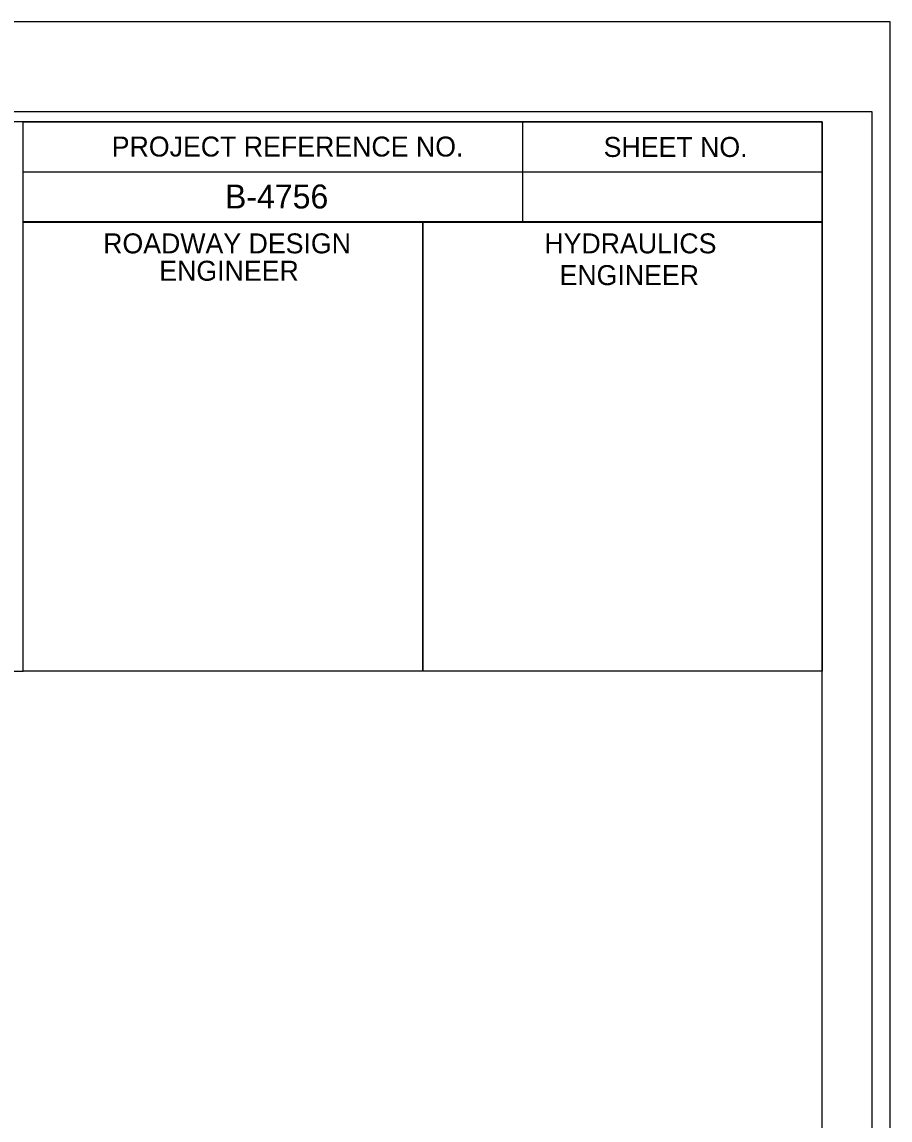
# Model space of a CAD drawing. Extents: x 2431000 to 2534000, y 645879 to 714000.
# Drawn here: x 2465319.4 to 2465536.7, y 677241.9 to 677516.9 of the extents above; entities that cross this region are included whole.
import ezdxf

# ---------------------------------------------------------------- set-up
doc = ezdxf.new("R2010")
doc.units = 0
for name, color, linetype in [('KHA_LOGO', 7, 'Continuous'), ('Sheet Plan CELL', 7, 'Continuous'), ('Sheet Plot Border Inside CELL', 7, 'Continuous'), ('Sheet Plot Border Outside CELL', 7, 'Continuous'), ('Sheet Typical CELL', 7, 'Continuous')]:
    doc.layers.add(name, color=color, linetype=linetype)

msp = doc.modelspace()

# ---------------------------------------------------------------- linework, layer by layer
at = {"layer": 'KHA_LOGO'}
msp.add_lwpolyline([(2465219.65, 677354.33), (2465319.65, 677354.33), (2465319.65, 677491.88), (2465219.65, 677491.88)], close=True, dxfattribs=at)
at = {"layer": 'Sheet Plan CELL'}
for points in [[(2465319.65, 677466.78), (2465419.7, 677466.78), (2465419.7, 677354.28), (2465319.65, 677354.28)], [(2465419.7, 677466.78), (2465519.7, 677466.78), (2465519.7, 677354.28), (2465419.7, 677354.28)]]:
    msp.add_lwpolyline(points, close=True, dxfattribs=at)
at = {"layer": 'Sheet Plot Border Inside CELL'}
msp.add_lwpolyline([(2463866.2, 676439.38), (2465532.2, 676439.38), (2465532.2, 677494.38), (2463866.2, 677494.38)], close=True, dxfattribs=at)
at = {"layer": 'Sheet Plot Border Outside CELL'}
msp.add_lwpolyline([(2463853.2, 676416.88), (2465536.7, 676416.88), (2465536.7, 677516.88), (2463853.2, 677516.88)], close=True, dxfattribs=at)
at = {"layer": 'Sheet Typical CELL'}
for p, q in [((2465444.7, 677491.83), (2465444.7, 677466.83)), ((2465319.65, 677479.33), (2465519.7, 677479.33))]:
    msp.add_line(p, q, dxfattribs=at)
for points in [[(2465519.7, 677491.88), (2464019.7, 677491.88), (2464019.7, 676441.88), (2465519.7, 676441.88)], [(2465319.65, 677491.88), (2465519.7, 677491.88), (2465519.7, 677466.83), (2465319.65, 677466.83)]]:
    msp.add_lwpolyline(points, close=True, dxfattribs=at)

# ---------------------------------------------------------------- texts
at = {"layer": 'Sheet Plan CELL'}
for s, height, p in [('B-4756', 6, (2465370.19, 677470.17)), ('HYDRAULICS', 5, (2465450.15, 677458.93)), ('ENGINEER', 5, (2465453.95, 677450.98))]:
    msp.add_text(s, height=height, dxfattribs=at).set_placement(p)
at = {"layer": 'Sheet Typical CELL'}
for s, height, p in [('PROJECT REFERENCE NO.', 5.0001, (2465341.85, 677483.18)), ('SHEET NO.', 5, (2465465, 677483.08)), ('ROADWAY DESIGN', 5.0001, (2465339.7, 677458.93)), ('ENGINEER', 5, (2465353.75, 677452.08))]:
    msp.add_text(s, height=height, dxfattribs=at).set_placement(p)

doc.saveas('drawing.dxf')
